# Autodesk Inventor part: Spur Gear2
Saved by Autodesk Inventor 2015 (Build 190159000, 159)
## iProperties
Created: 2014-08
Part Number: Spur Gear2
Material: Steel
Document SubType Name: Modeling
Designer: User
Categories: <?xml version="1.0" encoding="UTF-16"?> <MemberInstance><Categories><FamilyTemplate><FamilyTemplateParameter ValueType="xs:double" Id="1" ObjectReferenceKey="da
Density: 1 g/cm^3
Appearance: Steel
CustomPartVersion: 1
Author: User
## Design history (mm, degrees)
sketch "Sketch1"
  geometry: C1 r 6.446 at (0, 0)
  constraints: 1 centre point
  dimensions: "d0" = 12.89292 diameter of C1 (= da_da)
extrude "Extrusion1" new body sketch "Sketch1" distance "d1" = 4 (= da_b); taper "d2" = 0 deg
workplane "Work Plane2"
sketch "Sketch2"
  geometry: C1 r 6.446 at (0, 0) reference; C2 r 5.65 at (0, 0)
  constraints: 1 centre point, 1 coincident
  dimensions: "d3" = 11.3 diameter of C2 (= da_dw)
feature "Pitch Diameter" sketch "Sketch2" dims "d4" = 10, "d5" = 0
workplane "Work Plane8"
workplane "Work Plane9"
feature "Spur Gear" dims "da_b" = 4, "da_d" = 11.48758, "da_aw" = 11.3, "da_da" = 12.89292, "da_df" = 9.30708, "da_dw" = 11.3, angle "da_beta" = 40 deg, "da_lefttooth" = 0, "da_righttooth" = 10
body "Solid1"
body "Srf1"
other parameters: "d16" = 11.3 (= da_aw), "d17" = 0, "d34" = 2.85599 (computed from da_z), "d39" = 0, "d41" = 0, "d43" = 11.3 (= da_aw), "d46" = 11.3 (= da_aw), "d47" = 0, "d48" = 0
